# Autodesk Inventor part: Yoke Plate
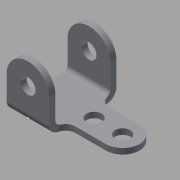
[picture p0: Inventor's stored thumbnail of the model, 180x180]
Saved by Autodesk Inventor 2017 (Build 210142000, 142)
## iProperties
Created: 2011-04
Part Number: Yoke Plate
Material: Generic
Document SubType Name: Modeling
Designer: Dell
Density: 1 g/cm^3
Appearance: Default
Author: Dell
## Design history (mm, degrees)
sketch "Sketch1"
  geometry: 1 further point
sketch "Sketch2"
  geometry: L1 (28.5, 36.5)-(28.5, -7.5); L2 (-28.5, -7.5)-(28.5, -7.5); L3 (-28.5, 36.5)-(-28.5, -7.5); C1 r 10 at (0, 36.5); A1 r 28.5 centre (0, 36.5) between (28.5, 36.5) and (-28.5, 36.5); 2 further points
  constraints: 6 end point, 2 centre point, 2 point on circle, 2 tangent, 2 vertical, 1 coincident, 1 perpendicular, 1 other
  dimensions: "d0" = 57 distance of L2.start L1.end; "d1" = 36.5 distance of point (0, 0) C1.centre; "d2" = 28.5 distance from line of L1 point (0, 0); "d3" = 20 diameter of C1; "d24" = 7.5 distance from line of point (0, 0) L2
extrude "Extrusion1" new body sketch "Sketch2" distance "d4" = 89; taper "d5" = 0 deg
sketch "Sketch3"
  geometry: L1 (44, 89)-(0, 89) reference; L2 (-28.588, 8)-(36.5, 8); L3 (36.5, 8)-(36.5, 81); L4 (36.5, 81)-(-28.588, 81); L5 (-28.588, 8)-(-28.588, 81); L6 (-28.5, 89)-(0, 89) reference; 3 further points
  constraints: 8 end point, 1 perpendicular
  dimensions: "d6" = 73 distance of L2.start L4.end; "d9" = 8 distance between parallel lines of L1 L4
extrude "Extrusion2" cut sketch "Sketch3" distance "d10" = 89; taper "d11" = 0 deg
sketch "Sketch4"
  geometry: L1 (0, 58.08)-(53.5, 58.08); L2 (53.5, 13.58)-(0, 13.58); L3 (0, 13.58)-(0, 58.08); L4 (0, 35.83)-(93.365, 35.83); L5 (0, 73)-(0, 0) reference; C1 r 10 at (53.5, 35.83); C2 r 10 at (15.5, 35.83); A1 r 22.25 centre (53.5, 35.83) between (53.5, 13.58) and (53.5, 58.08); 1 further point
  constraints: 8 end point, 3 centre point, 2 horizontal, 2 point on circle, 1 coincident, 1 collinear, 1 equal radius, 1 horizontal alignment, 1 parallel, 1 perpendicular, 1 point on line, 1 tangent
  dimensions: "d12" = 44.5 diameter of A1; "d13" = 44.5 distance between parallel lines of L2 L1; "d14" = 20 diameter of C1; "d15" = 38 distance of A1.centre C2.centre; "d23" = 15.5 distance from line of C2.centre L3
extrude "Extrusion3" join sketch "Sketch4" stored distance "d16" = 89; taper "d17" = 0 deg
fillet "Fillet1" dims "d18" = 12.7
fillet "Fillet2" dims "d19" = 6.35
fillet "Fillet3" dims "d20" = 12.75
body "Solid1"
